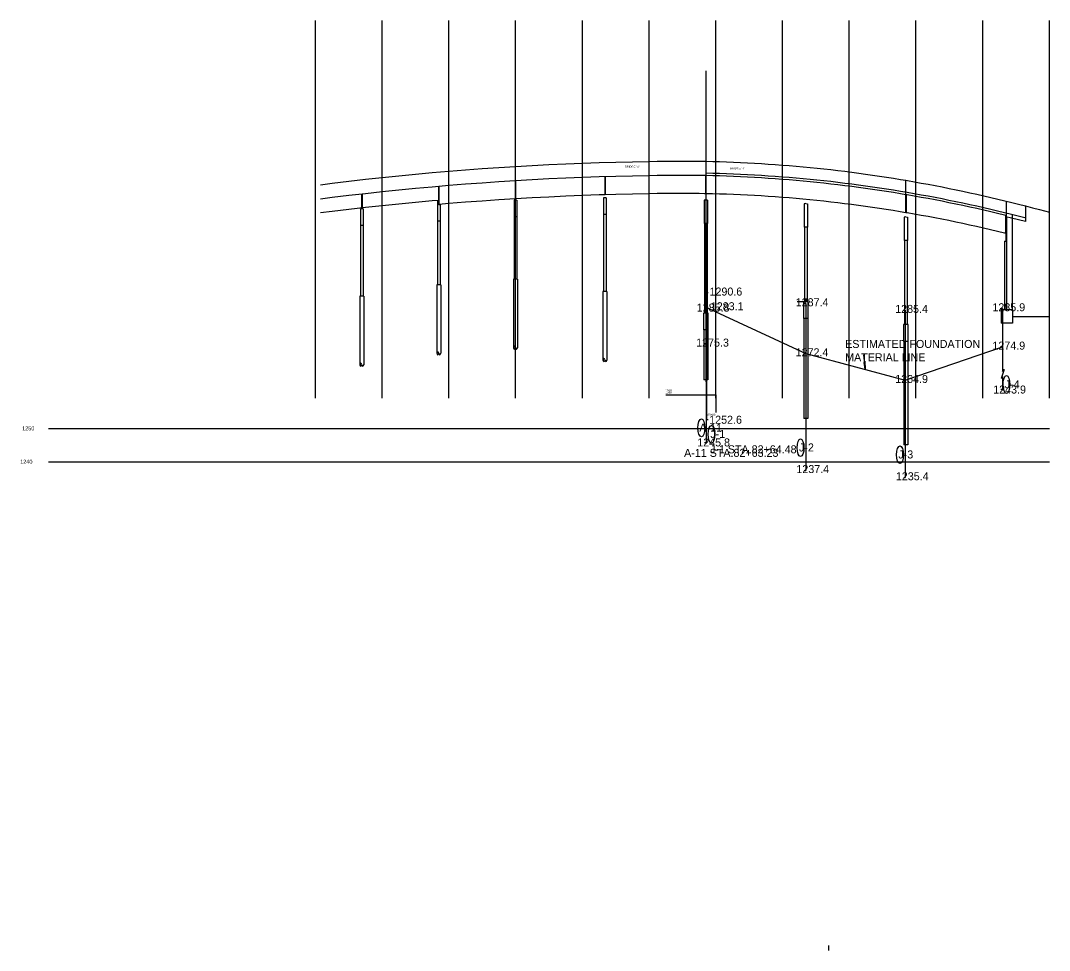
# Model space of a CAD drawing. Extents: x 2151751 to 2157567, y 143368 to 148435.
import ezdxf

# ---------------------------------------------------------------- set-up
doc = ezdxf.new("R2010")
doc.units = 0
for name, color, linetype in [('11', 7, 'Continuous'), ('BORE', 7, 'Continuous'), ('PR_Align', 7, 'Continuous'), ('PR_Bridge', 7, 'Continuous'), ('PR_Bridge_Pier', 7, 'Continuous'), ('PR_Storm_Conc_Pipe', 7, 'Continuous'), ('PR_Storm_Inlet_CICI', 7, 'Continuous'), ('PR_Storm_Txt', 7, 'Continuous'), ('T_BORE', 7, 'Continuous'), ('XSEC_Section_Grid_Major', 7, 'Continuous')]:
    doc.layers.add(name, color=color, linetype=linetype)

msp = doc.modelspace()

# ---------------------------------------------------------------- linework, layer by layer
at = {"layer": '11'}
for p, q in [((2157052.6, 147950.1), (2157053.2, 148004.6)), ((2157053.2, 148004.6), (2157201.8, 147935.6)), ((2157350.9, 147895.6), (2157496.7, 147945.6)), ((2157201.8, 147935.6), (2157350.9, 147895.6))]:
    msp.add_line(p, q, dxfattribs=at)
at = {"layer": 'BORE'}
for p, q in [((2157053.2, 148026.6), (2157053.2, 147836.6)), ((2157055.6, 148026.6), (2157053.2, 148026.6)), ((2157055.6, 148004.6), (2157053.2, 148004.6)), ((2157198.5, 148010.6), (2157201.8, 148010.6)), ((2157201.8, 148010.6), (2157201.8, 147760.6)), ((2157050.2, 148002.6), (2157052.6, 148002.6)), ((2157052.6, 148002.6), (2157052.6, 147802.6)), ((2157347.5, 148000.6), (2157350.9, 148000.6)), ((2157350.9, 148000.6), (2157350.9, 147749.8)), ((2157493.3, 148003.1), (2157496.7, 148003.1)), ((2157496.7, 148003.1), (2157496.7, 147908.8)), ((2157050.2, 147950.1), (2157052.6, 147950.1)), ((2157493.3, 147945.6), (2157496.7, 147945.6)), ((2157199.2, 147935.6), (2157201.8, 147935.6)), ((2157498.9, 147911.9), (2157494.7, 147898.4)), ((2157496.7, 147908.8), (2157498.9, 147911.9)), ((2157347.5, 147895.6), (2157350.9, 147895.6)), ((2157496.7, 147901.4), (2157494.7, 147898.4)), ((2157496.7, 147901.4), (2157496.7, 147882.4)), ((2157494.3, 147882.4), (2157496.7, 147882.4)), ((2157055.6, 147836.6), (2157053.2, 147836.6)), ((2157050.2, 147802.6), (2157052.6, 147802.6)), ((2157199.4, 147760.6), (2157201.8, 147760.6)), ((2157348.5, 147749.8), (2157350.9, 147749.8))]:
    msp.add_line(p, q, dxfattribs=at)
msp.add_lwpolyline([(2157290.3, 147924.3), (2157291, 147912.1), (2157289.5, 147922.4)], close=True, dxfattribs=at)
msp.add_open_spline([(2157289.9, 147923.3), (2157288.6, 147936.5), (2157287.7, 147931.4), (2157289.2, 147929.9), (2157288.3, 147930.1)], degree=3, dxfattribs=at)
at = {"layer": 'PR_Align'}
msp.add_lwpolyline([(2157051.8, 148206.3), (2157062.3, 148206), (2157072.7, 148205.8), (2157083.1, 148205.4), (2157093.5, 148205), (2157103.9, 148204.6), (2157114.3, 148204.1), (2157124.8, 148203.5), (2157135.2, 148202.9), (2157145.6, 148202.2), (2157156, 148201.5), (2157166.4, 148200.7), (2157176.8, 148199.9), (2157187.3, 148199), (2157197.7, 148198.1), (2157208.1, 148197.1), (2157218.5, 148196), (2157228.9, 148194.9), (2157239.3, 148193.8), (2157249.8, 148192.6), (2157260.2, 148191.3), (2157270.6, 148190), (2157281, 148188.6), (2157291.4, 148187.2), (2157312.3, 148184.2), (2157322.7, 148182.6), (2157333.1, 148180.9), (2157343.5, 148179.2), (2157353.9, 148177.5), (2157364.3, 148175.7), (2157374.8, 148173.8), (2157385.2, 148171.9), (2157395.6, 148169.9), (2157406, 148167.9), (2157416.4, 148165.8), (2157426.8, 148163.7), (2157437.3, 148161.5), (2157447.7, 148159.3), (2157458.1, 148157), (2157468.5, 148154.6), (2157478.9, 148152.2), (2157489.3, 148149.8), (2157499.8, 148147.3), (2157510.2, 148144.7), (2157531.9, 148139.3)], dxfattribs=at)
at = {"layer": 'PR_Bridge'}
for p, q in [((2156816.9, 148218.8), (2156841.9, 148220)), ((2156841.9, 148220), (2156866.9, 148221)), ((2156866.9, 148221), (2156891.9, 148221.9)), ((2156891.9, 148221.9), (2156916.9, 148222.6)), ((2156916.9, 148222.6), (2156941.9, 148223.2)), ((2156941.9, 148223.2), (2156966.9, 148223.7)), ((2156966.9, 148223.7), (2156979, 148223.9)), ((2156979, 148223.9), (2156991.9, 148224)), ((2156991.9, 148224), (2157016.9, 148224.1)), ((2157016.9, 148224.1), (2157041.9, 148223.9)), ((2157042, 148223.9), (2157050.3, 148223.8)), ((2157050.2, 148223.8), (2157051.8, 148223.8)), ((2157051.8, 148223.8), (2157051.8, 148202.8)), ((2156591.9, 148202.1), (2156616.9, 148204.5)), ((2156616.9, 148204.5), (2156641.9, 148206.8)), ((2156641.9, 148206.8), (2156666.9, 148208.9)), ((2156666.9, 148208.9), (2156691.9, 148210.9)), ((2156691.9, 148210.9), (2156716.9, 148212.8)), ((2156716.9, 148212.8), (2156741.9, 148214.5)), ((2156741.9, 148214.5), (2156766.9, 148216.1)), ((2156766.9, 148216.1), (2156791.9, 148217.5)), ((2156791.9, 148217.5), (2156816.9, 148218.8)), ((2156474.3, 148188.8), (2156491.9, 148191)), ((2156491.9, 148191), (2156516.9, 148194)), ((2156516.9, 148194), (2156541.9, 148196.8)), ((2156541.9, 148196.8), (2156566.9, 148199.5)), ((2156566.9, 148199.5), (2156591.9, 148202.1)), ((2156666.9, 148187.9), (2156691.9, 148189.9)), ((2156691.9, 148189.9), (2156716.9, 148191.8)), ((2156716.9, 148191.8), (2156741.9, 148193.5)), ((2156741.9, 148193.5), (2156766.9, 148195.1)), ((2156766.2, 148195.1), (2156766.2, 148168.3)), ((2156766.8, 148195.1), (2156766.8, 148168.4)), ((2156766.9, 148195.1), (2156791.9, 148196.5)), ((2156791.9, 148196.5), (2156816.9, 148197.8)), ((2156816.9, 148197.8), (2156841.9, 148199)), ((2156841.9, 148199), (2156866.9, 148200)), ((2156866.9, 148200), (2156891.9, 148200.9)), ((2156891.9, 148200.9), (2156916.9, 148201.6)), ((2156900.4, 148201.2), (2156900.4, 148174.2)), ((2156901, 148201.2), (2156901, 148174.2)), ((2156916.9, 148201.6), (2156941.9, 148202.2)), ((2156941.9, 148202.2), (2156966.9, 148202.7)), ((2156966.9, 148202.7), (2156979, 148202.9)), ((2156979, 148202.9), (2156991.9, 148203)), ((2156991.9, 148203), (2157016.9, 148203.1)), ((2157016.9, 148203.1), (2157041.9, 148202.9)), ((2157041.9, 148202.9), (2157050.3, 148202.8)), ((2157050.3, 148202.8), (2157051.8, 148202.8)), ((2157051.5, 148202.8), (2157051.5, 148175.8)), ((2157052.2, 148202.8), (2157052.2, 148175.8)), ((2157351.8, 148174.3), (2157351.8, 148195.3)), ((2156491.9, 148170), (2156516.9, 148173)), ((2156516.9, 148173), (2156541.9, 148175.8)), ((2156535.7, 148175.1), (2156535.7, 148154.2)), ((2156536.7, 148175.2), (2156536.7, 148154.3)), ((2156541.9, 148175.8), (2156566.9, 148178.5)), ((2156566.9, 148178.5), (2156591.9, 148181.1)), ((2156591.9, 148181.1), (2156616.9, 148183.5)), ((2156616.9, 148183.5), (2156641.9, 148185.8)), ((2156641.9, 148185.8), (2156666.9, 148187.9)), ((2156651.4, 148186.6), (2156651.4, 148165.7)), ((2156652, 148186.6), (2156652, 148159.9)), ((2156841.9, 148172), (2156866.9, 148173)), ((2156866.9, 148173), (2156891.9, 148173.9)), ((2156891.9, 148173.9), (2156900.4, 148174.2)), ((2156901, 148174.2), (2156916.9, 148174.6)), ((2156916.9, 148174.6), (2156941.9, 148175.2)), ((2156941.9, 148175.2), (2156966.9, 148175.7)), ((2156966.9, 148175.7), (2156979, 148175.9)), ((2156979, 148175.9), (2156991.9, 148176)), ((2156991.9, 148176), (2157016.9, 148176.1)), ((2157016.9, 148176.1), (2157041.9, 148175.9)), ((2157041.9, 148175.9), (2157050.2, 148175.8)), ((2157050.3, 148175.8), (2157051.5, 148175.8)), ((2157351.7, 148147.3), (2157351.7, 148174.4)), ((2157351.8, 148174.3), (2157351.9, 148174.3)), ((2157352, 148174.3), (2157352, 148147.3)), ((2156474.3, 148167.8), (2156491.9, 148170)), ((2156541.9, 148154.9), (2156566.9, 148157.6)), ((2156566.9, 148157.6), (2156591.9, 148160.2)), ((2156591.9, 148160.2), (2156616.9, 148162.6)), ((2156616.9, 148162.6), (2156641.9, 148164.9)), ((2156641.9, 148164.9), (2156651.4, 148165.7)), ((2156652, 148159.7), (2156666.9, 148160.9)), ((2156666.9, 148160.9), (2156691.9, 148162.9)), ((2156691.9, 148162.9), (2156716.9, 148164.8)), ((2156716.9, 148164.8), (2156741.9, 148166.5)), ((2156741.9, 148166.5), (2156766.9, 148168.1)), ((2156766.9, 148168.1), (2156791.9, 148169.5)), ((2156791.9, 148169.5), (2156816.9, 148170.8)), ((2156816.9, 148170.8), (2156841.9, 148172)), ((2157502.6, 148141.1), (2157502.6, 148164.1)), ((2156474.3, 148146.9), (2156491.9, 148149.1)), ((2156491.9, 148149.1), (2156516.9, 148152.1)), ((2156516.9, 148152.1), (2156541.9, 148154.9)), ((2157501.2, 148143.4), (2157501.2, 148116.3)), ((2157501.8, 148137.7), (2157501.8, 148143.3)), ((2157511.8, 148001.1), (2157511.8, 148144.3)), ((2157531.8, 148139.3), (2157531.8, 148156.7)), ((2157552, 148151.4), (2157566.9, 148147.4)), ((2157501.8, 148137.7), (2157501.8, 148104.2)), ((2157502.8, 148141.1), (2157502.8, 148001.1)), ((2157531.8, 148133.7), (2157531.8, 148139.2)), ((2157499.8, 148104.2), (2157501.8, 148104.2)), ((2157499.8, 148104.2), (2157499.8, 148001.1)), ((2157494.8, 148001.1), (2157494.8, 147981.1)), ((2157511.8, 148001.1), (2157494.8, 148001.1)), ((2157511.8, 148001.1), (2157511.8, 147981.1)), ((2157511.8, 147991.1), (2157566.9, 147991.1)), ((2157511.8, 147981.1), (2157494.8, 147981.1))]:
    msp.add_line(p, q, dxfattribs=at)
for points in [[(2157051.9, 148223.8), (2157062.3, 148223.5), (2157072.7, 148223.3), (2157083.1, 148222.9), (2157093.5, 148222.5), (2157104, 148222.1), (2157114.4, 148221.6), (2157124.8, 148221), (2157135.2, 148220.4), (2157145.6, 148219.7), (2157156.1, 148219), (2157166.5, 148218.2), (2157176.9, 148217.4), (2157187.3, 148216.5), (2157197.7, 148215.6), (2157208.2, 148214.6), (2157218.6, 148213.5), (2157229, 148212.4), (2157239.4, 148211.3), (2157249.8, 148210.1), (2157260.3, 148208.8), (2157270.7, 148207.5), (2157281.1, 148206.1), (2157291.5, 148204.7), (2157312.4, 148201.7), (2157322.8, 148200.1), (2157333.2, 148198.4), (2157343.6, 148196.7), (2157351.8, 148195.3)], [(2157051.8, 148202.8), (2157062.3, 148202.5), (2157072.7, 148202.3), (2157083.1, 148201.9), (2157093.5, 148201.5), (2157103.9, 148201.1), (2157114.3, 148200.6), (2157124.8, 148200), (2157135.2, 148199.4), (2157145.6, 148198.7), (2157156, 148198), (2157166.4, 148197.2), (2157176.8, 148196.4), (2157187.3, 148195.5), (2157197.7, 148194.6), (2157208.1, 148193.6), (2157218.5, 148192.5), (2157228.9, 148191.4), (2157239.3, 148190.3), (2157249.7, 148189.1), (2157260.2, 148187.8), (2157270.6, 148186.5), (2157281, 148185.1), (2157291.4, 148183.7), (2157312.2, 148180.7), (2157322.7, 148179.1), (2157333.1, 148177.4), (2157343.5, 148175.7), (2157351.8, 148174.3)], [(2157351.8, 148195.3), (2157354, 148195), (2157364.5, 148193.2), (2157374.9, 148191.3), (2157385.3, 148189.4), (2157395.7, 148187.4), (2157406.2, 148185.4), (2157416.6, 148183.3), (2157427, 148181.2), (2157437.4, 148179), (2157447.8, 148176.8), (2157458.3, 148174.5), (2157468.7, 148172.1), (2157479.1, 148169.7), (2157489.5, 148167.3), (2157499.9, 148164.8), (2157510.4, 148162.2), (2157520.8, 148159.6), (2157531.2, 148156.9), (2157541.6, 148154.2), (2157552, 148151.4)], [(2157052.2, 148175.8), (2157062.2, 148175.5), (2157072.6, 148175.3), (2157083.1, 148174.9), (2157093.5, 148174.5), (2157103.9, 148174.1), (2157114.3, 148173.6), (2157124.7, 148173), (2157135.1, 148172.4), (2157145.5, 148171.7), (2157155.9, 148171), (2157166.3, 148170.2), (2157176.7, 148169.4), (2157187.2, 148168.5), (2157197.6, 148167.6), (2157208, 148166.6), (2157218.4, 148165.5), (2157228.8, 148164.4), (2157239.2, 148163.3), (2157249.6, 148162.1), (2157260, 148160.8), (2157270.4, 148159.5), (2157280.8, 148158.1), (2157291.3, 148156.7), (2157312.1, 148153.7), (2157322.5, 148152.1), (2157332.9, 148150.4), (2157343.3, 148148.8), (2157351.7, 148147.3)], [(2157351.9, 148174.3), (2157353.9, 148174), (2157364.3, 148172.2), (2157374.7, 148170.3), (2157385.2, 148168.4), (2157395.6, 148166.4), (2157406, 148164.4), (2157416.4, 148162.3), (2157426.8, 148160.2), (2157437.2, 148158), (2157447.6, 148155.8), (2157458.1, 148153.5), (2157468.5, 148151.1), (2157478.9, 148148.7), (2157489.3, 148146.3), (2157499.7, 148143.8), (2157501.8, 148143.3)], [(2157352, 148147.3), (2157353.7, 148147), (2157364.1, 148145.2), (2157374.5, 148143.3), (2157385, 148141.4), (2157395.4, 148139.5), (2157405.8, 148137.4), (2157416.2, 148135.4), (2157426.6, 148133.2), (2157437, 148131), (2157447.4, 148128.8), (2157457.8, 148126.5), (2157468.2, 148124.2), (2157478.6, 148121.8), (2157489.1, 148119.3), (2157499.5, 148116.8), (2157501.2, 148116.4)], [(2157501.8, 148141.3), (2157510.1, 148139.3), (2157520.5, 148136.6), (2157531, 148134), (2157531.8, 148133.7)]]:
    msp.add_lwpolyline(points, dxfattribs=at)
at = {"layer": 'PR_Bridge_Pier'}
for p, q in [((2156651.7, 148164.3), (2156649.7, 148164.3)), ((2156649.7, 148164.3), (2156649.7, 148038.8)), ((2156651.7, 148164.3), (2156651.7, 148158.4)), ((2156653.7, 148158.4), (2156651.7, 148158.4)), ((2156653.7, 148158.4), (2156653.7, 148038.8)), ((2156768.5, 148165.8), (2156764.5, 148165.8)), ((2156764.5, 148165.8), (2156764.5, 148047)), ((2156768.5, 148165.8), (2156768.5, 148047)), ((2156902.7, 148169.2), (2156898.7, 148169.2)), ((2156898.7, 148169.2), (2156898.7, 148028.6)), ((2156902.7, 148169.2), (2156902.7, 148028.6)), ((2157054.3, 148165.8), (2157049.3, 148165.8)), ((2157049.3, 148165.8), (2157049.3, 148130.8)), ((2157054.3, 148165.8), (2157054.3, 148130.8)), ((2157201.8, 148160.8), (2157199.3, 148160.1)), ((2157199.3, 148160.1), (2157199.3, 148125.1)), ((2157201.8, 148160.8), (2157204.3, 148160.1)), ((2157204.3, 148160.1), (2157204.3, 148125.1)), ((2156534.2, 148152.7), (2156534.2, 148021.6)), ((2156538.2, 148152.7), (2156534.2, 148152.7)), ((2156538.2, 148152.7), (2156538.2, 148021.6)), ((2156902.7, 148144.2), (2156898.7, 148144.2)), ((2156538.2, 148127.7), (2156534.2, 148127.7)), ((2156653.7, 148134.3), (2156649.7, 148134.3)), ((2156768.5, 148140.8), (2156764.5, 148140.8)), ((2157054.3, 148130.8), (2157049.3, 148130.8)), ((2157049.8, 148130.8), (2157049.8, 147996.4)), ((2157053.8, 148130.8), (2157053.8, 147996.4)), ((2157351.8, 148140.6), (2157349.3, 148140)), ((2157349.3, 148140), (2157349.3, 148105)), ((2157351.8, 148140.6), (2157354.3, 148140)), ((2157354.3, 148140), (2157354.3, 148105)), ((2157204.3, 148125.1), (2157199.3, 148125.1)), ((2157199.8, 148125.1), (2157199.8, 148013.3)), ((2157203.8, 148125.1), (2157203.8, 148013.3)), ((2157354.3, 148105), (2157349.3, 148105)), ((2157349.8, 148105), (2157349.8, 147979)), ((2157353.8, 148105), (2157353.8, 147979)), ((2156654.7, 148038.8), (2156648.7, 148038.8)), ((2156648.7, 148038.8), (2156648.7, 147936.2)), ((2156654.7, 148038.8), (2156654.7, 147936.2)), ((2156769.5, 148047), (2156763.5, 148047)), ((2156763.5, 148047), (2156763.5, 147944.4)), ((2156769.5, 148047), (2156769.5, 147944.4)), ((2156533.2, 148021.6), (2156533.2, 147919)), ((2156539.2, 148021.6), (2156533.2, 148021.6)), ((2156539.2, 148021.6), (2156539.2, 147919)), ((2156897.7, 148028.6), (2156897.7, 147926)), ((2156903.7, 148028.6), (2156897.7, 148028.6)), ((2156903.7, 148028.6), (2156903.7, 147926)), ((2157205.3, 148013.3), (2157198.3, 148013.3)), ((2157198.3, 148013.3), (2157198.3, 147988.3)), ((2157205.3, 147988.3), (2157205.3, 148013.3)), ((2157055.3, 147996.4), (2157048.3, 147996.4)), ((2157048.3, 147996.4), (2157048.3, 147971.4)), ((2157055.3, 147971.4), (2157055.3, 147996.4)), ((2157205.3, 147988.3), (2157198.3, 147988.3)), ((2157198.8, 147988.3), (2157198.8, 147838.4)), ((2157204.8, 147988.3), (2157204.8, 147838.4)), ((2157355.3, 147979), (2157348.3, 147979)), ((2157348.3, 147979), (2157348.3, 147954)), ((2157355.3, 147954), (2157355.3, 147979)), ((2157055.3, 147971.4), (2157048.3, 147971.4)), ((2157048.8, 147971.4), (2157048.8, 147896.4)), ((2157054.8, 147971.4), (2157054.8, 147896.4)), ((2157355.3, 147954), (2157348.3, 147954)), ((2157348.8, 147954), (2157348.8, 147799)), ((2157354.8, 147954), (2157354.8, 147799)), ((2157054.8, 147896.4), (2157048.8, 147896.4)), ((2157204.8, 147838.4), (2157198.8, 147838.4)), ((2157354.8, 147799), (2157348.8, 147799))]:
    msp.add_line(p, q, dxfattribs=at)
for centre, start_param, end_param in [((2156765, 147933.6), 5.67722, 6.889151), ((2156765, 147955.2), 2.535627, 3.747558), ((2156768, 147955.2), 2.535627, 3.747558), ((2156650.2, 147925.4), 5.67722, 6.889151), ((2156650.2, 147947), 2.535627, 3.747558), ((2156653.2, 147947), 2.535627, 3.747558), ((2156899.2, 147915.2), 5.67722, 6.889151), ((2156534.7, 147908.2), 5.67722, 6.889151), ((2156534.7, 147929.8), 2.535627, 3.747558), ((2156537.7, 147929.8), 2.535627, 3.747558), ((2156899.2, 147936.8), 2.535627, 3.747558), ((2156902.2, 147936.8), 2.535627, 3.747558)]:
    msp.add_ellipse(centre, major_axis=(0, 13.2), ratio=0.2, start_param=start_param, end_param=end_param, dxfattribs=at)
at = {"layer": 'PR_Storm_Conc_Pipe'}
for p, q in [((2156992, 147873.6), (2157066.9, 147873.6)), ((2156992, 147873.6), (2157066.9, 147873.6)), ((2156992, 147873.6), (2157066.9, 147873.6)), ((2157003.9, 147873.6), (2157066.9, 147873.6)), ((2157066.9, 147873.6), (2157066.9, 147847.3)), ((2156066.9, 147823.6), (2157566.9, 147823.6)), ((2156066.9, 147773.6), (2157566.9, 147773.6))]:
    msp.add_line(p, q, dxfattribs=at)
msp.add_lwpolyline([(2157201.8, 148018.3), (2157201.8, 148013.3), (2157188.7, 148013.3)], dxfattribs=at)
at = {"layer": 'PR_Storm_Inlet_CICI'}
msp.add_line((2157051.8, 148359.4), (2157051.8, 147893.4), dxfattribs=at)
at = {"layer": 'PR_Storm_Txt'}
msp.add_line((2157235.7, 147048.7), (2157235.7, 147041.2), dxfattribs=at)
at = {"layer": 'T_BORE'}
for centre, major_axis in [((2157502.5, 147889.3), (0, -13.4)), ((2157045.3, 147824.3), (0, -13.4)), ((2157060.5, 147814.7), (0, 13.4)), ((2157194, 147794.6), (0, -13.4)), ((2157343, 147784.1), (0, -13.4))]:
    msp.add_ellipse(centre, major_axis=major_axis, ratio=0.379178, dxfattribs=at)
at = {"layer": 'XSEC_Section_Grid_Major'}
for p, q in [((2156466.9, 147868.6), (2156466.9, 148434.7)), ((2156566.9, 147868.6), (2156566.9, 148434.7)), ((2156666.9, 147868.6), (2156666.9, 148434.7)), ((2156766.9, 147868.6), (2156766.9, 148434.7)), ((2156866.9, 147868.6), (2156866.9, 148434.7)), ((2156966.9, 147868.6), (2156966.9, 148434.7)), ((2157066.9, 147868.6), (2157066.9, 148434.7)), ((2157166.9, 147868.6), (2157166.9, 148434.7)), ((2157266.9, 147868.6), (2157266.9, 148434.7)), ((2157366.9, 147868.6), (2157366.9, 148434.7)), ((2157466.9, 147868.6), (2157466.9, 148434.7)), ((2157566.9, 147868.6), (2157566.9, 148434.7))]:
    msp.add_line(p, q, dxfattribs=at)

# ---------------------------------------------------------------- texts
at = {"layer": 'BORE'}
for s, p in [('1290.6', (2157057.5, 148022.6)), ('1283.1', (2157059.4, 148000.6)), ('1252.6', (2157057, 147830.5))]:
    msp.add_text(s, height=12, dxfattribs=at).set_placement(p)
for s, p in [('1287.4', (2157186.7, 148006.6)), ('1285.4', (2157335.8, 147996.6)), ('1285.9', (2157481.5, 147999.1)), ('1272.4', (2157186.6, 147931.6)), ('ESTIMATED FOUNDATION ', (2157260.8, 147944.1)), ('1274.9', (2157481.5, 147941.6)), ('MATERIAL LINE', (2157260.8, 147924.1)), ('1264.9', (2157335.8, 147891.6)), ('1243.9', (2157482.7, 147875.8)), ('1237.4', (2157187.7, 147756.6)), ('1235.4', (2157336.8, 147745.8))]:
    msp.add_text(s, height=12, rotation=360, dxfattribs=at).set_placement(p)
at = {"layer": 'PR_Storm_Conc_Pipe'}
for s, height, p in [('BRIDGE "A"', 3, (2156930.7, 148214.2)), ('BRIDGE "J"', 3, (2157088.5, 148212)), ('1260', 3, (2156991.6, 147879)), ('1260', 3, (2156991.6, 147875.7)), ('83+00', 3, (2157054.6, 147842.5)), ('A-11 STA.82+63.23', 12, (2157019.4, 147780.9)), ('J-1 STA.82+64.48', 12, (2157058.2, 147786.2))]:
    msp.add_text(s, height=height, rotation=360, dxfattribs=at).set_placement(p)
for s, p in [('1250', (2156027.2, 147820.6)), ('1240', (2156024.3, 147770.6))]:
    msp.add_text(s, height=6, dxfattribs=at).set_placement(p)
at = {"layer": 'T_BORE'}
for s, p in [('1285.8', (2157038.3, 147998.6)), ('1275.3', (2157037.5, 147946.1)), ('J-4', (2157500, 147883.6)), ('A-11', (2157042.3, 147818.7)), ('1245.8', (2157039.1, 147796.5)), ('J-2', (2157191.6, 147789)), ('J-3', (2157340.5, 147778.5))]:
    msp.add_text(s, height=12, rotation=360, dxfattribs=at).set_placement(p)
msp.add_text('J-1', height=12, dxfattribs=at).set_placement((2157058.7, 147809.1))

doc.saveas('drawing.dxf')
